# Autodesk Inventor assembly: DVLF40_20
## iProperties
Created: 2009-11
Part Number: DVLF40_20
Document SubType Name: Assembly
Designer: TB
Mass: 457.822 g
Surface Area: 1062.11 cm^2
Volume: 457.822 cm^3
Density: 1 g/cm^3
Description: KM DVLF 40/20 - 100 mm
Slaglengde: 100.000 mm
Author: TB
